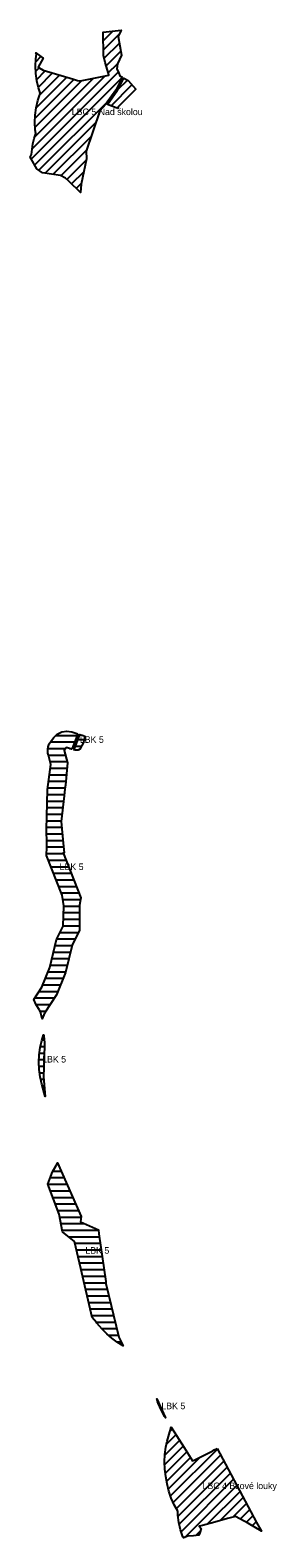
# Model space of a CAD drawing. Extents: x -477054 to -472307, y -1158904 to -1149471.
# Drawn here: x -476614 to -476314, y -1153676 to -1151839 of the extents above; entities that cross this region are included whole.
import ezdxf

# ---------------------------------------------------------------- set-up
doc = ezdxf.new("R2010")
doc.units = 0
doc.layers.add('16', color=7, linetype='Continuous')
doc.layers.add('19', color=7, linetype='Continuous')

msp = doc.modelspace()

# ---------------------------------------------------------------- linework, layer by layer
at = {"layer": '16'}
for p, q in [((-476525.2, -1151852.1), (-476513.6, -1151840.5)), ((-476525.1, -1151863.3), (-476505.7, -1151843.9)), ((-476524.1, -1151873.6), (-476505.7, -1151855.2)), ((-476607.5, -1151877.8), (-476601.2, -1151871.5)), ((-476521.7, -1151882.6), (-476504, -1151864.8)), ((-476519.2, -1151891.3), (-476508.2, -1151880.3)), ((-476613, -1151996.4), (-476507.1, -1151890.6)), ((-476612, -1151984.1), (-476523, -1151895.1)), ((-476608.9, -1151969.7), (-476537.2, -1151898)), ((-476608.8, -1152003.6), (-476502.3, -1151897.1)), ((-476607.5, -1151889.1), (-476603.5, -1151885.1)), ((-476606.8, -1151933.7), (-476569.8, -1151896.7)), ((-476606.4, -1151899.3), (-476595.9, -1151888.8)), ((-476604.4, -1151908.7), (-476587.2, -1151891.5)), ((-476603.1, -1151918.6), (-476578.5, -1151894.1)), ((-476608.2, -1151946.4), (-476561.2, -1151899.3)), ((-476608.2, -1151957.7), (-476551.3, -1151900.8)), ((-476515.9, -1151931.5), (-476490.5, -1151906.1)), ((-476507.5, -1151911.7), (-476496, -1151900.3)), ((-476603.8, -1152009.9), (-476519.6, -1151925.7)), ((-476507.8, -1151934.7), (-476507.6, -1151934.5)), ((-476596.1, -1152013.5), (-476534.4, -1151951.7)), ((-476586.2, -1152014.9), (-476540.2, -1151968.9)), ((-476576.6, -1152016.6), (-476546, -1151986)), ((-476569.7, -1152021.1), (-476545.8, -1151997.2)), ((-476563.9, -1152026.5), (-476548.8, -1152011.5)), ((-476558.2, -1152032.1), (-476551.8, -1152025.8)), ((-476589.7, -1152706.6), (-476560.3, -1152706.6)), ((-476583, -1152698.6), (-476557, -1152698.6)), ((-476556.1, -1152703.8), (-476548.7, -1152703.8)), ((-476592.7, -1152714.6), (-476570.8, -1152714.6)), ((-476592.2, -1152722.6), (-476571.4, -1152722.6)), ((-476566.5, -1152714.6), (-476563.5, -1152714.6)), ((-476559.2, -1152711.8), (-476551.8, -1152711.8)), ((-476589.9, -1152730.6), (-476569.2, -1152730.6)), ((-476589.6, -1152738.6), (-476569.4, -1152738.6)), ((-476591.7, -1152754.6), (-476571, -1152754.6)), ((-476590.7, -1152746.6), (-476570.2, -1152746.6)), ((-476593.4, -1152778.6), (-476573.7, -1152778.6)), ((-476593.2, -1152770.6), (-476572.8, -1152770.6)), ((-476592.8, -1152762.6), (-476571.9, -1152762.6)), ((-476593.9, -1152794.6), (-476575.6, -1152794.6)), ((-476593.6, -1152786.6), (-476574.7, -1152786.6)), ((-476594.3, -1152810.6), (-476576, -1152810.6)), ((-476594.1, -1152802.6), (-476576.5, -1152802.6)), ((-476594.3, -1152818.6), (-476575.3, -1152818.6)), ((-476594.2, -1152826.6), (-476574.6, -1152826.6)), ((-476593.9, -1152834.6), (-476573.7, -1152834.6)), ((-476594.4, -1152842.6), (-476573.9, -1152842.6)), ((-476592.3, -1152850.6), (-476570.8, -1152850.6)), ((-476589.1, -1152858.6), (-476567.6, -1152858.6)), ((-476586, -1152866.6), (-476564.5, -1152866.6)), ((-476582.8, -1152874.6), (-476561.3, -1152874.6)), ((-476579.6, -1152882.6), (-476558.1, -1152882.6)), ((-476576.5, -1152890.6), (-476555, -1152890.6)), ((-476574.5, -1152898.6), (-476552.9, -1152898.6)), ((-476573.3, -1152906.6), (-476554.2, -1152906.6)), ((-476574, -1152922.6), (-476554.3, -1152922.6)), ((-476573.6, -1152914.6), (-476554.2, -1152914.6)), ((-476578, -1152938.6), (-476555.7, -1152938.6)), ((-476574.3, -1152930.6), (-476554.3, -1152930.6)), ((-476585.8, -1152962.6), (-476565.3, -1152962.6)), ((-476584, -1152954.6), (-476563.4, -1152954.6)), ((-476581.9, -1152946.6), (-476559.6, -1152946.6)), ((-476589.6, -1152978.6), (-476569.1, -1152978.6)), ((-476587.7, -1152970.6), (-476567.2, -1152970.6)), ((-476595.7, -1152994.6), (-476574.1, -1152994.6)), ((-476592.4, -1152986.6), (-476571, -1152986.6)), ((-476608.8, -1153018.6), (-476584.9, -1153018.6)), ((-476603.5, -1153010.6), (-476580.6, -1153010.6)), ((-476599, -1153002.6), (-476577.4, -1153002.6)), ((-476607, -1153026.6), (-476590.1, -1153026.6)), ((-476602.2, -1153034.6), (-476595.3, -1153034.6)), ((-476600.1, -1153042.6), (-476599.2, -1153042.6)), ((-476600.1, -1153069.7), (-476597.2, -1153069.7)), ((-476603.2, -1153085.7), (-476597.2, -1153085.7)), ((-476602, -1153077.7), (-476597, -1153077.7)), ((-476603.8, -1153093.7), (-476597.3, -1153093.7)), ((-476603.7, -1153101.7), (-476597.6, -1153101.7)), ((-476603, -1153109.7), (-476597.9, -1153109.7)), ((-476601.6, -1153117.7), (-476597.9, -1153117.7)), ((-476599.7, -1153125.7), (-476597.2, -1153125.7)), ((-476597.4, -1153133.7), (-476596.5, -1153133.7)), ((-476582.1, -1153221.5), (-476579.9, -1153221.5)), ((-476590, -1153237.5), (-476572.9, -1153237.5)), ((-476586.5, -1153229.5), (-476576.4, -1153229.5)), ((-476592.6, -1153245.5), (-476569.4, -1153245.5)), ((-476589.6, -1153253.5), (-476565.8, -1153253.5)), ((-476586.6, -1153261.5), (-476562.3, -1153261.5)), ((-476583.7, -1153269.5), (-476558.8, -1153269.5)), ((-476580.7, -1153277.5), (-476555.3, -1153277.5)), ((-476578.4, -1153285.5), (-476552.2, -1153285.5)), ((-476576.9, -1153293.5), (-476548.4, -1153293.5)), ((-476575.5, -1153301.5), (-476531.2, -1153301.5)), ((-476567.8, -1153309.5), (-476530.3, -1153309.5)), ((-476560, -1153317.5), (-476529.1, -1153317.5)), ((-476558.1, -1153325.5), (-476528, -1153325.5)), ((-476556.2, -1153333.5), (-476526.8, -1153333.5)), ((-476554.3, -1153341.5), (-476525.7, -1153341.5)), ((-476552.4, -1153349.5), (-476524.5, -1153349.5)), ((-476550.5, -1153357.5), (-476523.4, -1153357.5)), ((-476548.6, -1153365.5), (-476522.3, -1153365.5)), ((-476546.7, -1153373.5), (-476520.4, -1153373.5)), ((-476544.8, -1153381.5), (-476518.5, -1153381.5)), ((-476543, -1153389.5), (-476516.6, -1153389.5)), ((-476541.1, -1153397.5), (-476514.6, -1153397.5)), ((-476539.2, -1153405.5), (-476512.7, -1153405.5)), ((-476534.1, -1153413.5), (-476510.7, -1153413.5)), ((-476527.1, -1153421.5), (-476508.8, -1153421.5)), ((-476519, -1153429.5), (-476506.8, -1153429.5)), ((-476509, -1153437.5), (-476503.6, -1153437.5)), ((-476448.2, -1153562.1), (-476436.9, -1153550.8)), ((-476444.4, -1153547), (-476441.3, -1153543.9)), ((-476450.5, -1153587.1), (-476428.1, -1153564.6)), ((-476450.3, -1153575.5), (-476432.5, -1153557.7)), ((-476443.5, -1153625.3), (-476386.4, -1153568.2)), ((-476449.6, -1153597.5), (-476423.7, -1153571.5)), ((-476448.1, -1153607.2), (-476419.3, -1153578.4)), ((-476446.1, -1153616.5), (-476407.4, -1153577.9)), ((-476440.3, -1153633.3), (-476382.5, -1153575.6)), ((-476436.5, -1153640.9), (-476378.5, -1153582.9)), ((-476434.3, -1153650.1), (-476374.6, -1153590.3)), ((-476432.8, -1153659.9), (-476370.7, -1153597.7)), ((-476430.5, -1153668.9), (-476366.8, -1153605.1)), ((-476426.1, -1153675.8), (-476362.9, -1153612.5)), ((-476398.5, -1153659.5), (-476358.9, -1153619.9)), ((-476383, -1153655.3), (-476355, -1153627.3)), ((-476367.7, -1153651.3), (-476351.1, -1153634.7)), ((-476358.7, -1153653.6), (-476347.2, -1153642.1)), ((-476351.3, -1153657.5), (-476343.3, -1153649.5)), ((-476344, -1153661.6), (-476339.3, -1153656.9)), ((-476412.7, -1153673.6), (-476407.4, -1153668.3)), ((-476336.8, -1153665.7), (-476335.1, -1153664))]:
    msp.add_line(p, q, dxfattribs=at)
for points in [[(-476502.1, -1151896.7), (-476510.1, -1151912.3), (-476522.6, -1151929.9), (-476529.6, -1151937.6), (-476546.2, -1151986.8), (-476545.6, -1151996), (-476552.1, -1152027), (-476553.1, -1152037.1), (-476566.9, -1152023.6), (-476571.2, -1152019.8), (-476577.3, -1152016.2), (-476599.2, -1152013), (-476606.1, -1152008.2), (-476613.2, -1151996), (-476614.3, -1151993.9), (-476612.6, -1151990.7), (-476612, -1151984.2), (-476610.9, -1151977.7), (-476609.4, -1151971.4), (-476607.5, -1151965.2), (-476608.1, -1151960.8), (-476608.5, -1151951.8), (-476608.1, -1151942.8), (-476606.9, -1151933.9), (-476604.9, -1151925.2), (-476603.1, -1151918.9), (-476602.3, -1151915.5), (-476604.2, -1151909.7), (-476606.2, -1151901), (-476607.4, -1151892.1), (-476607.8, -1151883.1), (-476607.4, -1151874.2), (-476606.6, -1151868.4), (-476607.6, -1151867), (-476598.5, -1151873.5), (-476604.6, -1151884.3), (-476603.4, -1151885.1), (-476598.4, -1151888.1), (-476561.6, -1151899.2), (-476556.8, -1151900.7), (-476554.8, -1151900.9), (-476553.1, -1151901.2), (-476518.4, -1151894.2), (-476519, -1151892), (-476522.9, -1151878.6), (-476525.1, -1151870), (-476525.3, -1151841.8), (-476503.6, -1151839.3), (-476507.1, -1151847), (-476503.1, -1151869.7), (-476508.1, -1151880.2), (-476508.9, -1151886.5), (-476506.6, -1151891.8), (-476505.3, -1151894.8)], [(-476507.7, -1151934.7), (-476509.6, -1151934), (-476520.4, -1151929.7), (-476507.9, -1151912.5), (-476500.5, -1151897.6), (-476495.1, -1151900.8), (-476485.8, -1151911.4), (-476507.1, -1151932.7)], [(-476386.6, -1153567.7), (-476339, -1153657.5), (-476332.6, -1153668.1), (-476348.4, -1153659.1), (-476364.6, -1153650.5), (-476374.3, -1153653), (-476389.7, -1153657.1), (-476404.7, -1153661.2), (-476408.7, -1153662.3), (-476406.2, -1153664.9), (-476407.9, -1153670.1), (-476409, -1153673.3), (-476415.5, -1153673.9), (-476422.3, -1153674.5), (-476427.9, -1153676.4), (-476428.5, -1153675), (-476431.3, -1153666.5), (-476433.3, -1153657.7), (-476434.5, -1153648.8), (-476434.8, -1153643.9), (-476439.1, -1153636.1), (-476442.6, -1153627.9), (-476445.4, -1153619.4), (-476447.4, -1153610.7), (-476449.1, -1153601.8), (-476450.3, -1153592.8), (-476450.7, -1153583.8), (-476450.3, -1153574.8), (-476449.1, -1153565.9), (-476447.4, -1153558.5), (-476444.5, -1153547.3), (-476444.1, -1153545.9), (-476442.8, -1153541.7), (-476426.9, -1153566.5), (-476416.7, -1153582.5), (-476413.3, -1153580.8), (-476392, -1153570.2), (-476390.2, -1153569.3)]]:
    msp.add_lwpolyline(points, close=True, dxfattribs=at)
at = {"layer": '19'}
for points in [[(-476556.3, -1152696.9), (-476563.4, -1152714.4), (-476563.9, -1152715.4), (-476570, -1152713.5), (-476572.9, -1152717.2), (-476568.7, -1152732.2), (-476571.5, -1152759.3), (-476572, -1152763.6), (-476573, -1152772.4), (-476576.6, -1152803.5), (-476574.3, -1152830.1), (-476573.8, -1152833.8), (-476572.9, -1152841.9), (-476574.3, -1152841.7), (-476552.6, -1152896.6), (-476552.9, -1152898.7), (-476554.2, -1152905.6), (-476554.4, -1152935.9), (-476563.3, -1152954.1), (-476571.2, -1152987.5), (-476582.3, -1153014.7), (-476596.8, -1153036.9), (-476599.8, -1153044.1), (-476601.7, -1153035.4), (-476603.4, -1153032.8), (-476606.9, -1153026.8), (-476610, -1153020.5), (-476600.1, -1153005.3), (-476590.3, -1152981.4), (-476582.2, -1152947.4), (-476574.3, -1152931.2), (-476573.3, -1152906.2), (-476575.4, -1152893.4), (-476594.5, -1152844.9), (-476593.9, -1152834.5), (-476594.2, -1152832.4), (-476594.2, -1152830), (-476594.4, -1152813.9), (-476593.1, -1152764.6), (-476589, -1152733.9), (-476592.2, -1152722.6), (-476592.5, -1152721.4), (-476592.7, -1152720.2), (-476592.8, -1152718.9), (-476592.9, -1152717.7), (-476592.9, -1152716.4), (-476592.8, -1152715.1), (-476592.6, -1152713.8), (-476592.4, -1152712.6), (-476592, -1152711.3), (-476591.6, -1152710.1), (-476591.1, -1152708.9), (-476588.5, -1152704.7), (-476585.6, -1152701), (-476581.4, -1152697.1), (-476575.9, -1152694.4), (-476569.9, -1152693.5), (-476563.8, -1152694.4)], [(-476556.1, -1152716.7), (-476559.7, -1152716.8), (-476561.1, -1152716.3), (-476560.4, -1152714.8), (-476553.7, -1152697.7), (-476549.9, -1152698.9), (-476548, -1152699.5), (-476549.1, -1152706.6), (-476553.7, -1152715.4)], [(-476598.1, -1153114.5), (-476596.1, -1153138.5), (-476600.2, -1153123.7), (-476602.3, -1153114.7), (-476603.5, -1153105.8), (-476603.9, -1153096.8), (-476603.5, -1153087.9), (-476602.3, -1153079), (-476600.3, -1153070.2), (-476598.1, -1153063.3), (-476597.7, -1153064.7), (-476597, -1153072.8), (-476597, -1153073.7), (-476597.3, -1153092.1)], [(-476506.3, -1153431.8), (-476501.3, -1153442.4), (-476508.3, -1153438.1), (-476514.8, -1153433.2), (-476521, -1153427.8), (-476526.7, -1153422), (-476533, -1153414.9), (-476533.6, -1153414.2), (-476538.7, -1153407.9), (-476552.7, -1153348.1), (-476560.4, -1153315.5), (-476575.1, -1153303.6), (-476579, -1153282.2), (-476592.7, -1153245.3), (-476590.6, -1153238.8), (-476587, -1153230.5), (-476582.7, -1153222.5), (-476580.9, -1153219.4), (-476580.9, -1153219.4), (-476552.1, -1153284.7), (-476553.1, -1153291.5), (-476531.2, -1153301.1), (-476530.8, -1153305.9), (-476522.4, -1153364.2), (-476522.1, -1153366.6)], [(-476452.1, -1153524.8), (-476449.5, -1153530.3), (-476450.7, -1153528.5), (-476454.9, -1153520.6), (-476458.4, -1153512.4), (-476459.2, -1153510.3), (-476460.3, -1153507.2), (-476459.9, -1153507.7), (-476455.3, -1153517.9)]]:
    msp.add_lwpolyline(points, close=True, dxfattribs=at)

# ---------------------------------------------------------------- texts
at = {"layer": '16'}
for s, p in [('LBC 5 Nad školou', (-476563.7, -1151942.8)), ('LBC 4 Bzové louky', (-476404.5, -1153617))]:
    msp.add_text(s, height=8, dxfattribs=at).set_placement(p)
at = {"layer": '19'}
for p in [(-476553.9, -1152707.7), (-476578.5, -1152862.7), (-476599.8, -1153097.2), (-476547.2, -1153330.2), (-476454.7, -1153519.7)]:
    msp.add_text('LBK 5', height=8, dxfattribs=at).set_placement(p)

doc.saveas('drawing.dxf')
